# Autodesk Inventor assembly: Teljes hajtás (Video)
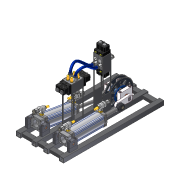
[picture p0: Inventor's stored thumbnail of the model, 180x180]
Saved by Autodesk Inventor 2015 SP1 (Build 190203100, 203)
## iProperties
Created: 2013-02
Part Number: Teljes hajtás (Video)
Document SubType Name: Assembly
Designer: Marci
MOTOR: 0,00 deg
Author: Marci
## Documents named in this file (19)
- C:\Users\TREINA11\Desktop\#01- Polymechanics and Automation\01 - 3D Models\Pneumatic System\Teljes hajtás (Video).iam
- C:\Users\TREINA11\Desktop\#01- Polymechanics and Automation\01 - 3D Models\Pneumatic System\Váz.iam
- C:\Users\TREINA11\Desktop\#01- Polymechanics and Automation\01 - 3D Models\Pneumatic System\Közdarab.ipt
- C:\Users\TREINA11\Desktop\#01- Polymechanics and Automation\01 - 3D Models\Pneumatic System\1827001604.ipt
- C:\Users\TREINA11\Desktop\#01- Polymechanics and Automation\01 - 3D Models\Pneumatic System\1827001611.ipt
- C:\Users\TREINA11\Desktop\#01- Polymechanics and Automation\01 - 3D Models\Pneumatic System\csapágyház.ipt
- C:\Users\TREINA11\Desktop\#01- Polymechanics and Automation\01 - 3D Models\Pneumatic System\Összerakva a henger.iam
- C:\Users\TREINA11\Desktop\#01- Polymechanics and Automation\01 - 3D Models\Pneumatic System\Főtengely összerakva.iam
- C:\Users\TREINA11\Desktop\#01- Polymechanics and Automation\01 - 3D Models\Pneumatic System\Szelep összerakva.iam
- C:\Users\TREINA11\Desktop\#01- Polymechanics and Automation\01 - 3D Models\Pneumatic System\Szelep.ipt
- C:\Users\TREINA11\Desktop\#01- Polymechanics and Automation\01 - 3D Models\Pneumatic System\1.4 12 gyorscsat.ipt
- C:\Users\TREINA11\Desktop\#01- Polymechanics and Automation\01 - 3D Models\Pneumatic System\Zárócsavar.ipt
- C:\Users\TREINA11\Desktop\#01- Polymechanics and Automation\01 - 3D Models\Pneumatic System\Lemez.ipt
- C:\Users\TREINA11\Desktop\#01- Polymechanics and Automation\01 - 3D Models\Pneumatic System\Lemez 2.ipt
- C:\Users\TREINA11\Desktop\#01- Polymechanics and Automation\01 - 3D Models\Pneumatic System\Teljes hajtás.Tube and Pipe Runs05.iam
- C:\Users\TREINA11\Desktop\#01- Polymechanics and Automation\01 - 3D Models\Pneumatic System\Atuador.iam
- C:\Users\TREINA11\Desktop\#01- Polymechanics and Automation\01 - 3D Models\Pneumatic System\Eixo.ipt
- C:\Users\TREINA11\Desktop\#01- Polymechanics and Automation\01 - 3D Models\Pneumatic System\Ponta.ipt
- C:\Users\TREINA11\Desktop\#01- Polymechanics and Automation\01 - 3D Models\Pneumatic System\DIN 912 - M8 x 1,25 x 30 x 26,875.ipt
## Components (69 placed, 18 different names)
1. Váz:1 [sub-assembly] — Flush:1, Mate:1, Flush:2, Mate:2, Flush:3, Flush:4, Mate:3, Flush:5, Flush:6, Mate:4, Flush:7, Flush:8, Mate:14, Mate:15, Flush:17, Flush:18, Flush:19, Flush:20, Flush:25, Mate:30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
2. Közdarab:1 — Flush:1, Mate:1, Flush:2, Mate:5, Flush:9, Flush:10
3. Közdarab:2 — Mate:2, Flush:3, Flush:4, Mate:6, Flush:11, Flush:12
4. Közdarab:3 — Mate:3, Flush:5, Flush:6, Flush:13, Mate:7, Flush:14
5. Közdarab:4 — Mate:4, Flush:7, Flush:8, Mate:8, Flush:16
6. 1827001604:1 — Mate:5, Flush:9, Flush:10, Mate:12, Mate:13, Inserir:19, Inserir:22
7. 1827001604:2 — Mate:6, Flush:11, Flush:12, Mate:29, Inserir:20, Inserir:21
8. 1827001604:3 — Flush:13, Mate:7, Flush:14, Mate:9, Mate:10, Inserir:23, Inserir:24
9. 1827001604:4 — Mate:8, Flush:16, Mate:11, Inserir:25, Inserir:26
10. 1827001611:1 — Mate:9, Mate:10, Mate:11, Insert:15, Insert:16, Insert:17, Insert:18, Mate:67, Mate:68, Angle:2
11. 1827001611:2 — Mate:12, Mate:13, Mate:59, Mate:60, Angle:1, Insert:2, Insert:3, Insert:4, Insert:5
12. csapágyház:1 — Mate:14, Flush:18, Flush:20, Mate:22, Mate:23, Inserir:29, Inserir:30
13. csapágyház:2 — Mate:15, Flush:17, Flush:19, Inserir:27, Inserir:28
14. Összerakva a henger:1 [sub-assembly] — Mate:61, Mate:62, Mate:63
15. Összerakva a henger:2 [sub-assembly] — Mate:69, Mate:70, Mate:72
16. Főtengely összerakva:1 [sub-assembly] — Mate:22, Mate:23, Mate:65, Mate:71, MOTOR
17. Szelep összerakva:1 [sub-assembly] — Mate:28, Mate:29, Mate:30, Flush:27, Flush:28, Flush:30, Mate:55, Mate:56
18. Szelep összerakva:2 [sub-assembly] — Flush:26, Flush:27, Flush:28, Flush:29, Mate:58
19. Szelep:1 — Flush:31, Mate:31, Flush:32, Mate:34, Mate:35, Mate:36, Mate:38, Mate:40, Mate:42, Mate:44, Mate:47, Mate:48, Mate:51, Mate:54, Flush:34
20. Szelep:2 — Flush:29, Flush:30, Flush:31, Mate:31, Flush:32, Mate:32, Mate:33, Mate:37, Mate:39, Mate:41, Mate:43, Mate:45, Mate:46, Mate:49, Mate:50, Mate:52, Flush:33
21. 1.4 12 gyorscsat:1 — Mate:32, Mate:33
22. 1.4 12 gyorscsat:2 — Mate:34, Mate:35
23. 1.4 12 gyorscsat:3 — Mate:36, Mate:38
24. 1.4 12 gyorscsat:4 — Mate:37, Mate:39
25. Zárócsavar:1 — Mate:46, Mate:49
26. Zárócsavar:2 — Mate:47, Mate:48
27. Zárócsavar:3 — Mate:40, Mate:51
28. Zárócsavar:4 — Mate:41, Mate:50
29. Zárócsavar:5 — Mate:43, Mate:45
30. Zárócsavar:6 — Mate:42, Mate:44
31. Lemez:1 — Mate:52, Flush:33, Mate:53, Flush:35
32. Lemez:2 — Mate:54, Flush:34, Flush:35, Flush:38
33. Lemez 2:1 — Mate:55, Mate:56, Mate:57, Flush:36, Flush:37
34. Lemez 2:2 — Flush:36, Mate:58, Flush:37
35. Tube & Pipe Runs 05 [sub-assembly]
36. Atuador:1 [sub-assembly] — Mate:59, Mate:60, Mate:61, Mate:62, Mate:63, Angle:1, Mate:64, Insert:6, Insert:7, Insert:8, Insert:9, Mate:75
37. Eixo:1 — Mate:64, Insert:1, Mate:75
38. Ponta:1 — Insert:1, Mate:65
39. DIN 912 - M8 x 1,25 x 30 x 26,875:1 — Insert:2
40. DIN 912 - M8 x 1,25 x 30 x 26,875:2 — Insert:3
41. DIN 912 - M8 x 1,25 x 30 x 26,875:3 — Insert:4
42. DIN 912 - M8 x 1,25 x 30 x 26,875:4 — Insert:5
43. DIN 912 - M8 x 1,25 x 30 x 26,875:5 — Insert:6
44. DIN 912 - M8 x 1,25 x 30 x 26,875:6 — Insert:7
45. DIN 912 - M8 x 1,25 x 30 x 26,875:7 — Insert:9
46. DIN 912 - M8 x 1,25 x 30 x 26,875:8 — Insert:8
47. Atuador:2 [sub-assembly] — Mate:67, Mate:68, Mate:69, Mate:70, Angle:2, Mate:72
48. Eixo:2
49. Ponta:2 — Mate:71
50. DIN 912 - M8 x 1,25 x 30 x 26,875:9 — Insert:16
51. DIN 912 - M8 x 1,25 x 30 x 26,875:10 — Insert:17
52. DIN 912 - M8 x 1,25 x 30 x 26,875:11 — Insert:18
53. DIN 912 - M8 x 1,25 x 30 x 26,875:12 — Insert:15
54. DIN 912 - M8 x 1,25 x 30 x 26,875:13
55. DIN 912 - M8 x 1,25 x 30 x 26,875:14
56. DIN 912 - M8 x 1,25 x 30 x 26,875:15
57. DIN 912 - M8 x 1,25 x 30 x 26,875:16
58. DIN 912 - M8 x 1,25 x 30 x 26,875:17 — Inserir:19
59. DIN 912 - M8 x 1,25 x 30 x 26,875:18 — Inserir:23
60. DIN 912 - M8 x 1,25 x 30 x 26,875:19 — Inserir:20
61. DIN 912 - M8 x 1,25 x 30 x 26,875:20 — Inserir:21
62. DIN 912 - M8 x 1,25 x 30 x 26,875:21 — Inserir:22
63. DIN 912 - M8 x 1,25 x 30 x 26,875:22 — Inserir:24
64. DIN 912 - M8 x 1,25 x 30 x 26,875:23 — Inserir:25
65. DIN 912 - M8 x 1,25 x 30 x 26,875:24 — Inserir:26
66. DIN 912 - M8 x 1,25 x 30 x 26,875:25 — Inserir:29
67. DIN 912 - M8 x 1,25 x 30 x 26,875:26 — Inserir:30
68. DIN 912 - M8 x 1,25 x 30 x 26,875:27 — Inserir:27
69. DIN 912 - M8 x 1,25 x 30 x 26,875:28 — Inserir:28
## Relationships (126: Mate 64, Flush 34, Insert 25, Angle 3)
- Flush:1: Váz:1 ↔ Közdarab:1
- Mate:1: Váz:1 ↔ Közdarab:1
- Flush:2: Váz:1 ↔ Közdarab:1
- Mate:2: Váz:1 ↔ Közdarab:2
- Flush:3: Váz:1 ↔ Közdarab:2
- Flush:4: Váz:1 ↔ Közdarab:2
- Mate:3: Váz:1 ↔ Közdarab:3
- Flush:5: Váz:1 ↔ Közdarab:3
- Flush:6: Váz:1 ↔ Közdarab:3
- Mate:4: Váz:1 ↔ Közdarab:4
- Flush:7: Váz:1 ↔ Közdarab:4
- Flush:8: Váz:1 ↔ Közdarab:4
- Mate:5: Közdarab:1 ↔ 1827001604:1
- Flush:9: Közdarab:1 ↔ 1827001604:1
- Flush:10: Közdarab:1 ↔ 1827001604:1
- Mate:6: Közdarab:2 ↔ 1827001604:2
- Flush:11: Közdarab:2 ↔ 1827001604:2
- Flush:12: Közdarab:2 ↔ 1827001604:2
- Flush:13: Közdarab:3 ↔ 1827001604:3
- Mate:7: Közdarab:3 ↔ 1827001604:3
- Flush:14: Közdarab:3 ↔ 1827001604:3
- Mate:8: Közdarab:4 ↔ 1827001604:4
- Flush:16: Közdarab:4 ↔ 1827001604:4
- Mate:9: 1827001604:3 ↔ 1827001611:1
- Mate:10: 1827001604:3 ↔ 1827001611:1
- Mate:11: 1827001604:4 ↔ 1827001611:1
- Mate:12: 1827001604:1 ↔ 1827001611:2
- Mate:13: 1827001604:1 ↔ 1827001611:2
- Mate:14: Váz:1 ↔ csapágyház:1
- Mate:15: Váz:1 ↔ csapágyház:2
- Flush:17: Váz:1 ↔ csapágyház:2
- Flush:18: Váz:1 ↔ csapágyház:1
- Flush:19: Váz:1 ↔ csapágyház:2
- Flush:20: Váz:1 ↔ csapágyház:1
- Mate:22: csapágyház:1 ↔ Főtengely összerakva:1
- Mate:23: csapágyház:1 ↔ Főtengely összerakva:1
- Flush:25: Váz:1
- Mate:28: Szelep összerakva:1
- Mate:29: 1827001604:2 ↔ Szelep összerakva:1
- Mate:30: Váz:1 ↔ Szelep összerakva:1
- Flush:26: Szelep összerakva:2
- Flush:27: Szelep összerakva:1 ↔ Szelep összerakva:2
- Flush:28: Szelep összerakva:1 ↔ Szelep összerakva:2
- Flush:29: Szelep összerakva:2 ↔ Szelep:2
- Flush:30: Szelep összerakva:1 ↔ Szelep:2
- Flush:31: Szelep:1 ↔ Szelep:2
- Mate:31: Szelep:1 ↔ Szelep:2
- Flush:32: Szelep:1 ↔ Szelep:2
- Mate:32: Szelep:2 ↔ 1.4 12 gyorscsat:1
- Mate:33: Szelep:2 ↔ 1.4 12 gyorscsat:1
- Mate:34: Szelep:1 ↔ 1.4 12 gyorscsat:2
- Mate:35: Szelep:1 ↔ 1.4 12 gyorscsat:2
- Mate:36: Szelep:1 ↔ 1.4 12 gyorscsat:3
- Mate:37: Szelep:2 ↔ 1.4 12 gyorscsat:4
- Mate:38: Szelep:1 ↔ 1.4 12 gyorscsat:3
- Mate:39: Szelep:2 ↔ 1.4 12 gyorscsat:4
- Mate:40: Szelep:1 ↔ Zárócsavar:3
- Mate:41: Szelep:2 ↔ Zárócsavar:4
- Mate:42: Szelep:1 ↔ Zárócsavar:6
- Mate:43: Szelep:2 ↔ Zárócsavar:5
- Mate:44: Szelep:1 ↔ Zárócsavar:6
- Mate:45: Szelep:2 ↔ Zárócsavar:5
- Mate:46: Szelep:2 ↔ Zárócsavar:1
- Mate:47: Szelep:1 ↔ Zárócsavar:2
- Mate:48: Szelep:1 ↔ Zárócsavar:2
- Mate:49: Szelep:2 ↔ Zárócsavar:1
- Mate:50: Szelep:2 ↔ Zárócsavar:4
- Mate:51: Szelep:1 ↔ Zárócsavar:3
- Mate:52: Szelep:2 ↔ Lemez:1
- Flush:33: Szelep:2 ↔ Lemez:1
- Mate:53: Váz:1 ↔ Lemez:1
- Mate:54: Szelep:1 ↔ Lemez:2
- Flush:34: Szelep:1 ↔ Lemez:2
- Flush:35: Lemez:1 ↔ Lemez:2
- Mate:55: Szelep összerakva:1 ↔ Lemez 2:1
- Mate:56: Szelep összerakva:1 ↔ Lemez 2:1
- Mate:57: Váz:1 ↔ Lemez 2:1
- Flush:36: Lemez 2:1 ↔ Lemez 2:2
- Mate:58: Szelep összerakva:2 ↔ Lemez 2:2
- Flush:37: Lemez 2:1 ↔ Lemez 2:2
- Mate:59: 1827001611:2 ↔ Atuador:1
- Mate:60: 1827001611:2 ↔ Atuador:1
- Mate:61: Összerakva a henger:1 ↔ Atuador:1
- Mate:62: Összerakva a henger:1 ↔ Atuador:1
- Mate:63: Összerakva a henger:1 ↔ Atuador:1
- Angle:1: 1827001611:2 ↔ Atuador:1
- Mate:64: Atuador:1 ↔ Eixo:1
- Insert:1: Eixo:1 ↔ Ponta:1
- Mate:65: Főtengely összerakva:1 ↔ Ponta:1
- Insert:2: 1827001611:2 ↔ DIN 912 - M8 x 1,25 x 30 x 26,875:1
- Insert:3: 1827001611:2 ↔ DIN 912 - M8 x 1,25 x 30 x 26,875:2
- Insert:4: 1827001611:2 ↔ DIN 912 - M8 x 1,25 x 30 x 26,875:3
- Insert:5: 1827001611:2 ↔ DIN 912 - M8 x 1,25 x 30 x 26,875:4
- Insert:6: Atuador:1 ↔ DIN 912 - M8 x 1,25 x 30 x 26,875:5
- Insert:7: Atuador:1 ↔ DIN 912 - M8 x 1,25 x 30 x 26,875:6
- Insert:8: Atuador:1 ↔ DIN 912 - M8 x 1,25 x 30 x 26,875:8
- Insert:9: Atuador:1 ↔ DIN 912 - M8 x 1,25 x 30 x 26,875:7
- Insert:15: 1827001611:1 ↔ DIN 912 - M8 x 1,25 x 30 x 26,875:12
- Insert:16: 1827001611:1 ↔ DIN 912 - M8 x 1,25 x 30 x 26,875:9
- Insert:17: 1827001611:1 ↔ DIN 912 - M8 x 1,25 x 30 x 26,875:10
- Insert:18: 1827001611:1 ↔ DIN 912 - M8 x 1,25 x 30 x 26,875:11
- Mate:67: 1827001611:1 ↔ Atuador:2
- Mate:68: 1827001611:1 ↔ Atuador:2
- Mate:69: Összerakva a henger:2 ↔ Atuador:2
- Mate:70: Összerakva a henger:2 ↔ Atuador:2
- Mate:71: Főtengely összerakva:1 ↔ Ponta:2
- Angle:2: 1827001611:1 ↔ Atuador:2
- Mate:72: Összerakva a henger:2 ↔ Atuador:2
- MOTOR [Angle]: Váz:1 ↔ Főtengely összerakva:1
- Inserir:19: 1827001604:1 ↔ DIN 912 - M8 x 1,25 x 30 x 26,875:17
- Inserir:20: 1827001604:2 ↔ DIN 912 - M8 x 1,25 x 30 x 26,875:19
- Inserir:21: 1827001604:2 ↔ DIN 912 - M8 x 1,25 x 30 x 26,875:20
- Inserir:22: 1827001604:1 ↔ DIN 912 - M8 x 1,25 x 30 x 26,875:21
- Inserir:23: 1827001604:3 ↔ DIN 912 - M8 x 1,25 x 30 x 26,875:18
- Inserir:24: 1827001604:3 ↔ DIN 912 - M8 x 1,25 x 30 x 26,875:22
- Inserir:25: 1827001604:4 ↔ DIN 912 - M8 x 1,25 x 30 x 26,875:23
- Inserir:26: 1827001604:4 ↔ DIN 912 - M8 x 1,25 x 30 x 26,875:24
- Inserir:27: csapágyház:2 ↔ DIN 912 - M8 x 1,25 x 30 x 26,875:27
- Inserir:28: csapágyház:2 ↔ DIN 912 - M8 x 1,25 x 30 x 26,875:28
- Inserir:29: csapágyház:1 ↔ DIN 912 - M8 x 1,25 x 30 x 26,875:25
- Inserir:30: csapágyház:1 ↔ DIN 912 - M8 x 1,25 x 30 x 26,875:26
- Flush:38: Váz:1 ↔ Lemez:2
- Mate:73: Váz:1
- Flush:39: Váz:1
- Mate:74: Váz:1
- Mate:75: Atuador:1 ↔ Eixo:1
## Named parameters: d116_d105 = 0, d117_d106 = 0, d118_d112 = 0, d119_d113 = 0, d120_d114 = 0, d121_d115 = 0
